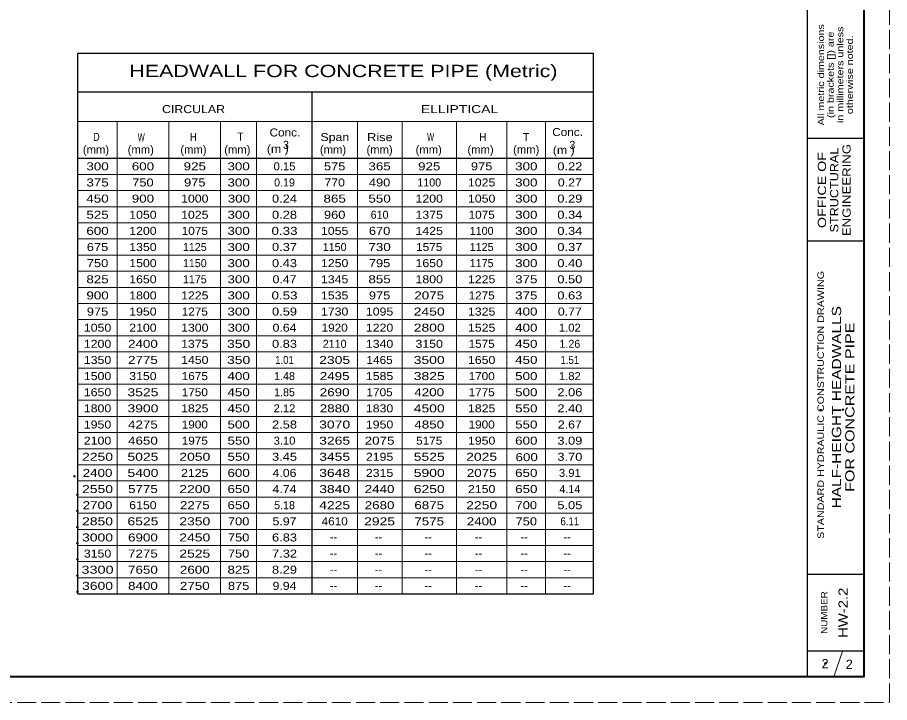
# Model space of a CAD drawing. Extents: x 685.4 to 719.4, y 1059.8 to 1105.8.
# Drawn here: x 702.44 to 719.44, y 1059.77 to 1073.13 of the extents above; entities that cross this region are included whole.
import ezdxf
from ezdxf.enums import TextEntityAlignment as Align

# ---------------------------------------------------------------- set-up
doc = ezdxf.new("R2010")
doc.units = 0
doc.header["$LTSCALE"] = 0.062
doc.header["$PDMODE"] = 32
doc.header["$PDSIZE"] = 0.031
doc.linetypes.add('LONG_DASHED', pattern=[7.5, 6, -1.5])
doc.layers.add('1', color=7, linetype='Continuous', lineweight=13)

msp = doc.modelspace()

# ---------------------------------------------------------------- linework, layer by layer
at = {"layer": '1', "lineweight": 25}
for p, q in [((717.84108, 1060.27067), (717.84108, 1081.27067)), ((718.94108, 1081.27067), (718.94108, 1060.27067)), ((703.62042, 1061.88917), (703.62042, 1072.433)), ((703.62042, 1072.433), (713.67225, 1072.433)), ((713.67225, 1061.88917), (713.67225, 1072.433)), ((703.62042, 1071.68142), (713.67225, 1071.68142)), ((708.18317, 1061.88917), (708.18317, 1071.68142)), ((718.94108, 1070.77067), (717.84108, 1070.77067)), ((703.62042, 1070.38517), (713.67225, 1070.38517)), ((718.94108, 1068.77067), (717.84108, 1068.77067)), ((718.94108, 1062.27067), (717.84108, 1062.27067)), ((703.62042, 1061.88917), (713.67225, 1061.88917)), ((718.94108, 1060.77067), (717.84108, 1060.77067))]:
    msp.add_line(p, q, dxfattribs=at)
at = {"layer": '1'}
for p, q in [((703.62042, 1071.10025), (713.67225, 1071.10025)), ((704.38225, 1061.88917), (704.38225, 1071.10025)), ((705.39258, 1061.88917), (705.39258, 1071.10025)), ((706.40208, 1061.88917), (706.40208, 1071.10025)), ((707.10417, 1061.88917), (707.10417, 1071.10025)), ((709.06775, 1061.88917), (709.06775, 1071.10025)), ((709.93908, 1061.88917), (709.93908, 1071.10025)), ((710.99742, 1061.88917), (710.99742, 1071.10025)), ((711.98225, 1061.88917), (711.98225, 1071.10025)), ((712.735, 1061.88917), (712.735, 1071.10025)), ((703.62042, 1070.0705), (713.67225, 1070.0705)), ((703.62042, 1069.75583), (713.67225, 1069.75583)), ((703.62042, 1069.44117), (713.67225, 1069.44117)), ((703.62042, 1069.1265), (713.67225, 1069.1265)), ((703.62042, 1068.81183), (713.67225, 1068.81183)), ((703.62042, 1068.49717), (713.67225, 1068.49717)), ((703.62042, 1068.1825), (713.67225, 1068.1825)), ((703.62042, 1067.86783), (713.67225, 1067.86783)), ((703.62042, 1067.55317), (713.67225, 1067.55317)), ((703.62042, 1067.2385), (713.67225, 1067.2385)), ((703.62042, 1066.92383), (713.67225, 1066.92383)), ((703.62042, 1066.60917), (713.67225, 1066.60917)), ((703.62042, 1066.2945), (713.67225, 1066.2945)), ((703.62042, 1065.97983), (713.67225, 1065.97983)), ((703.62042, 1065.66517), (713.67225, 1065.66517)), ((703.62042, 1065.3505), (713.67225, 1065.3505)), ((703.62042, 1065.03583), (713.67225, 1065.03583)), ((703.62042, 1064.72117), (713.67225, 1064.72117)), ((703.62042, 1064.4065), (713.67225, 1064.4065)), ((703.62042, 1064.09183), (713.67225, 1064.09183)), ((703.62042, 1063.77717), (713.67225, 1063.77717)), ((703.62042, 1063.4625), (713.67225, 1063.4625)), ((703.62042, 1063.14783), (713.67225, 1063.14783)), ((703.62042, 1062.83317), (713.67225, 1062.83317)), ((703.62042, 1062.5185), (713.67225, 1062.5185)), ((703.62042, 1062.20383), (713.67225, 1062.20383)), ((718.35775, 1060.27067), (718.52442, 1060.77067))]:
    msp.add_line(p, q, dxfattribs=at)
at = {"layer": '1', "linetype": 'LONG_DASHED'}
msp.add_lwpolyline([(685.44108, 1059.77067), (719.44108, 1059.77067), (719.44108, 1081.77067), (685.44108, 1081.77067)], close=True, dxfattribs=at)
at = {"layer": '1', "lineweight": 25}
msp.add_lwpolyline([(718.94108, 1060.27067), (687.44108, 1060.27067), (687.44108, 1081.27067)], dxfattribs=at)
at = {"layer": '1', "lineweight": 40}
msp.add_lwpolyline([(687.44108, 1081.27067), (718.94108, 1081.27067), (718.94108, 1060.27067), (687.44108, 1060.27067)], close=True, dxfattribs=at)
at = {"layer": '1'}
for p in [(718.0985, 1065.47667), (718.53133, 1065.484), (703.55342, 1064.18225), (703.611, 1063.82358), (703.611, 1063.50825), (703.611, 1063.19283), (703.611, 1062.8775), (703.611, 1062.56217), (703.611, 1062.24683), (703.611, 1061.9315), (718.18917, 1060.53442)]:
    msp.add_point(p, dxfattribs=at)

# ---------------------------------------------------------------- texts
for s, height, width, p in [('All metric dimensions', 0.125, 1.25, (718.16492, 1072.01275)), ('in millimeters unless', 0.125, 1.25, (718.53992, 1072.01279)), ('(in brackets []) are', 0.125, 1.25, (718.35242, 1072.01275)), ('otherwise noted.', 0.125, 1.25, (718.72742, 1072.01275)), ('OFFICE OF', 0.16, 1.3, (718.20283, 1069.76512)), ('STRUCTURAL', 0.16, 1.15, (718.44283, 1069.76512)), ('ENGINEERING', 0.16, 1.2, (718.68283, 1069.76521)), ('STANDARD HYDRAULIC CONSTRUCTION DRAWING', 0.125, 1.25, (718.161, 1065.57471)), ('HALF-HEIGHT HEADWALLS', 0.18, 1.25, (718.49692, 1065.53079)), ('FOR CONCRETE PIPE', 0.18, 1.3, (718.75692, 1065.53083)), ('HW-2.2', 0.18, 1.2, (718.62558, 1061.52104)), ('NUMBER', 0.125, 1.15, (718.22808, 1061.52475))]:
    msp.add_text(s, height=height, rotation=90, dxfattribs=dict(at, width=width)).set_placement(p, align=Align.CENTER)
for s, height, width, p in [('HEADWALL FOR CONCRETE PIPE (Metric)', 0.24, 1.3, (704.623, 1071.9675)), ('CIRCULAR', 0.156, 1.15, (705.2605, 1071.26567)), ('ELLIPTICAL', 0.156, 1.3, (710.30542, 1071.26558)), ('D', 0.156, 0.85, (703.91592, 1070.72442)), ('W', 0.156, 0.7, (704.78575, 1070.71775)), ('H', 0.156, 0.9, (705.8025, 1070.72108)), ('Conc.', 0.156, 1.1, (707.35508, 1070.81017)), ('Span', 0.156, 1.15, (708.34775, 1070.72058)), ('Rise', 0.156, 1.2, (709.25583, 1070.71942)), ('W', 0.156, 0.7, (710.4255, 1070.71942)), ('H', 0.156, 0.9, (711.44467, 1070.72108)), ('Conc.', 0.156, 1.1, (712.86567, 1070.818)), ('(mm)', 0.156, 1.05, (703.71675, 1070.47708)), ('(mm)', 0.156, 1.05, (704.58958, 1070.47708)), ('(mm)', 0.156, 1.05, (705.61642, 1070.47708)), ('(mm)', 0.156, 1.05, (706.47208, 1070.47708)), ('(m )', 0.156, 1.15, (707.30267, 1070.49067)), ('(mm)', 0.156, 1.05, (708.33758, 1070.47708)), ('(mm)', 0.156, 1.05, (709.24458, 1070.47708)), ('(mm)', 0.156, 1.05, (710.203, 1070.47708)), ('(mm)', 0.156, 1.05, (711.21275, 1070.47708)), ('(mm)', 0.156, 1.05, (712.10267, 1070.47708)), ('(m )', 0.156, 1.15, (712.87733, 1070.4695))]:
    msp.add_text(s, height=height, dxfattribs=dict(at, width=width)).set_placement(p)
for s, height, p in [('T', 0.156, (706.72317, 1070.73117)), ('T', 0.156, (712.29183, 1070.72108)), ('3', 0.156, (707.61658, 1070.5705)), ('3', 0.156, (713.19967, 1070.56892)), ('--', 0.16, (708.53008, 1062.922)), ('--', 0.16, (709.41008, 1062.922)), ('--', 0.16, (710.37525, 1062.922)), ('--', 0.16, (711.35458, 1062.922)), ('--', 0.16, (712.24875, 1062.922)), ('--', 0.16, (713.08625, 1062.922)), ('--', 0.16, (708.53008, 1062.60467)), ('--', 0.16, (709.41008, 1062.60467)), ('--', 0.16, (710.37525, 1062.60467)), ('--', 0.16, (711.35458, 1062.60467)), ('--', 0.16, (712.24875, 1062.60467)), ('--', 0.16, (713.08625, 1062.60467)), ('--', 0.16, (708.53008, 1062.28733)), ('--', 0.16, (709.41008, 1062.28733)), ('--', 0.16, (710.37525, 1062.28733)), ('--', 0.16, (711.35458, 1062.28733)), ('--', 0.16, (712.24875, 1062.28733)), ('--', 0.16, (713.08625, 1062.28733)), ('--', 0.16, (708.53008, 1061.97)), ('--', 0.16, (709.41008, 1061.97)), ('--', 0.16, (710.37525, 1061.97)), ('--', 0.16, (711.35458, 1061.97)), ('--', 0.16, (712.24875, 1061.97)), ('--', 0.16, (713.08625, 1061.97))]:
    msp.add_text(s, height=height, dxfattribs=at).set_placement(p)
for s, width, p in [('300', 1.25, (704.00254, 1070.14983)), ('600', 1.25, (704.88717, 1070.14983)), ('925', 1.25, (705.89808, 1070.14983)), ('300', 1.25, (706.75288, 1070.14983)), ('0.15', 1.05, (707.64696, 1070.14983)), ('575', 1.2, (708.62483, 1070.14983)), ('365', 1.25, (709.50004, 1070.14983)), ('925', 1.25, (710.46767, 1070.14983)), ('975', 1.2, (711.48992, 1070.14983)), ('300', 1.25, (712.35996, 1070.14983)), ('0.22', 1.2, (713.20887, 1070.14983)), ('375', 1.25, (704.00238, 1069.83517)), ('750', 1.2, (704.88712, 1069.83517)), ('975', 1.2, (705.89808, 1069.83517)), ('300', 1.25, (706.75288, 1069.83517)), ('770', 1.15, (708.62471, 1069.83517)), ('490', 1.2, (709.50004, 1069.83517)), ('1025', 1.15, (711.48987, 1069.83517)), ('300', 1.25, (712.35996, 1069.83517)), ('0.27', 1.15, (713.20892, 1069.83517)), ('450', 1.25, (704.00238, 1069.5205)), ('900', 1.25, (704.88717, 1069.5205)), ('1000', 1.15, (705.898, 1069.5205)), ('300', 1.25, (706.75771, 1069.5205)), ('0.24', 1.2, (707.647, 1069.5205)), ('865', 1.25, (708.62475, 1069.5205)), ('550', 1.25, (709.50017, 1069.5205)), ('1200', 1.15, (710.46767, 1069.5205)), ('1050', 1.15, (711.49004, 1069.5205)), ('300', 1.25, (712.35996, 1069.5205)), ('0.29', 1.2, (713.20896, 1069.5205)), ('525', 1.25, (704.00242, 1069.20583)), ('1050', 1.15, (704.88729, 1069.20583)), ('1025', 1.15, (705.89804, 1069.20583)), ('300', 1.25, (706.75288, 1069.20583)), ('0.28', 1.2, (707.64692, 1069.20583)), ('960', 1.2, (708.62471, 1069.20583)), ('1375', 1.15, (710.46771, 1069.20583)), ('1075', 1.1, (711.49004, 1069.20583)), ('300', 1.25, (712.35996, 1069.20583)), ('0.34', 1.2, (713.20892, 1069.20583)), ('600', 1.25, (704.00233, 1068.89117)), ('1200', 1.15, (704.88717, 1068.89117)), ('1075', 1.1, (705.89821, 1068.89117)), ('300', 1.25, (706.75288, 1068.89117)), ('0.33', 1.25, (707.647, 1068.89117)), ('1055', 1.15, (708.62479, 1068.89117)), ('670', 1.2, (709.50004, 1068.89117)), ('1425', 1.15, (710.46779, 1068.89117)), ('300', 1.25, (712.35996, 1068.89117)), ('0.34', 1.2, (713.20883, 1068.89117)), ('675', 1.2, (704.00238, 1068.5765)), ('1350', 1.15, (704.88712, 1068.5765)), ('300', 1.25, (706.75288, 1068.5765)), ('0.37', 1.2, (707.647, 1068.5765)), ('730', 1.25, (709.50013, 1068.5765)), ('1575', 1.1, (710.46775, 1068.5765)), ('300', 1.25, (712.35996, 1068.5765)), ('0.37', 1.2, (713.20892, 1068.5765)), ('750', 1.2, (704.00238, 1068.26183)), ('1500', 1.15, (704.88729, 1068.26183)), ('300', 1.25, (706.75288, 1068.26183)), ('0.43', 1.2, (707.64692, 1068.26183)), ('1250', 1.15, (708.62479, 1068.26183)), ('795', 1.2, (709.50008, 1068.26183)), ('1650', 1.15, (710.46762, 1068.26183)), ('300', 1.25, (712.35996, 1068.26183)), ('0.40', 1.2, (713.20892, 1068.26183)), ('825', 1.25, (704.00254, 1067.94717)), ('1650', 1.15, (704.88712, 1067.94717)), ('300', 1.25, (706.75288, 1067.94717)), ('0.47', 1.15, (707.647, 1067.94717)), ('1345', 1.15, (708.62471, 1067.94717)), ('855', 1.25, (709.50004, 1067.94717)), ('1800', 1.15, (710.46775, 1067.94717)), ('1225', 1.15, (711.48987, 1067.94717)), ('375', 1.25, (712.35987, 1067.94717)), ('0.50', 1.2, (713.20887, 1067.94717)), ('900', 1.25, (704.00242, 1067.6325)), ('1800', 1.15, (704.88717, 1067.6325)), ('1225', 1.15, (705.89804, 1067.6325)), ('300', 1.25, (706.75288, 1067.6325)), ('0.53', 1.25, (707.64704, 1067.6325)), ('1535', 1.15, (708.62475, 1067.6325)), ('975', 1.2, (709.50008, 1067.6325)), ('2075', 1.25, (710.46779, 1067.6325)), ('1275', 1.1, (711.49004, 1067.6325)), ('375', 1.25, (712.35987, 1067.6325)), ('0.63', 1.2, (713.20883, 1067.6325)), ('975', 1.2, (704.00233, 1067.31783)), ('1950', 1.15, (704.88717, 1067.31783)), ('1275', 1.1, (705.89821, 1067.31783)), ('300', 1.25, (706.75288, 1067.31783)), ('300', 1.25, (706.75288, 1067.31783)), ('0.59', 1.2, (707.64692, 1067.31783)), ('1730', 1.15, (708.62462, 1067.31783)), ('1095', 1.15, (709.50017, 1067.31783)), ('2450', 1.3, (710.46775, 1067.31783)), ('1325', 1.15, (711.48996, 1067.31783)), ('400', 1.25, (712.35983, 1067.31783)), ('0.77', 1.15, (713.20887, 1067.31783)), ('1050', 1.15, (704.00246, 1067.00317)), ('2100', 1.15, (704.88717, 1067.00317)), ('1300', 1.15, (705.89812, 1067.00317)), ('300', 1.25, (706.75288, 1067.00317)), ('0.64', 1.15, (707.647, 1067.00317)), ('1920', 1.1, (708.62479, 1067.00317)), ('1220', 1.15, (709.50008, 1067.00317)), ('2800', 1.3, (710.46775, 1067.00317)), ('1525', 1.15, (711.48996, 1067.00317)), ('400', 1.25, (712.35983, 1067.00317)), ('1.02', 1.05, (713.20879, 1067.00317)), ('1200', 1.15, (704.00233, 1066.6885)), ('2400', 1.25, (704.88717, 1066.6885)), ('1375', 1.15, (705.89804, 1066.6885)), ('350', 1.3, (706.75271, 1066.6885)), ('0.83', 1.2, (707.647, 1066.6885)), ('1340', 1.15, (709.50008, 1066.6885)), ('3150', 1.15, (710.46771, 1066.6885)), ('1575', 1.1, (711.48992, 1066.6885)), ('450', 1.25, (712.35987, 1066.6885)), ('1350', 1.15, (704.00238, 1066.37383)), ('2775', 1.25, (704.88712, 1066.37383)), ('1450', 1.15, (705.89804, 1066.37383)), ('350', 1.3, (706.75271, 1066.37383)), ('1.01', 0.9, (707.64704, 1066.37383)), ('2305', 1.3, (708.62479, 1066.37383)), ('1465', 1.1, (709.50008, 1066.37383)), ('3500', 1.3, (710.46762, 1066.37383)), ('1650', 1.15, (711.48987, 1066.37383)), ('450', 1.25, (712.35987, 1066.37383)), ('1.51', 0.9, (713.20879, 1066.37383)), ('1500', 1.15, (704.00246, 1066.05917)), ('3150', 1.15, (704.88712, 1066.05917)), ('1675', 1.1, (705.89804, 1066.05917)), ('400', 1.25, (706.75275, 1066.05917)), ('2495', 1.25, (708.62471, 1066.05917)), ('1585', 1.15, (709.50004, 1066.05917)), ('3825', 1.3, (710.46775, 1066.05917)), ('1700', 1.1, (711.48996, 1066.05917)), ('500', 1.25, (712.35987, 1066.05917)), ('1.82', 1.05, (713.20887, 1066.05917)), ('1650', 1.15, (704.00229, 1065.7445)), ('3525', 1.3, (704.88712, 1065.7445)), ('1750', 1.1, (705.89804, 1065.7445)), ('450', 1.25, (706.75279, 1065.7445)), ('2690', 1.25, (708.62471, 1065.7445)), ('1705', 1.1, (709.50021, 1065.7445)), ('4200', 1.25, (710.46767, 1065.7445)), ('1775', 1.1, (711.48996, 1065.7445)), ('500', 1.25, (712.35987, 1065.7445)), ('2.06', 1.2, (713.20883, 1065.7445)), ('1800', 1.15, (704.00242, 1065.42983)), ('3900', 1.3, (704.88712, 1065.42983)), ('1825', 1.15, (705.89808, 1065.42983)), ('450', 1.25, (706.75279, 1065.42983)), ('2.12', 1.05, (707.64688, 1065.42983)), ('2880', 1.25, (708.62471, 1065.42983)), ('1830', 1.15, (709.50017, 1065.42983)), ('4500', 1.3, (710.46775, 1065.42983)), ('1825', 1.15, (711.48992, 1065.42983)), ('550', 1.25, (712.35992, 1065.42983)), ('2.40', 1.2, (713.20883, 1065.42983)), ('1950', 1.15, (704.00242, 1065.11517)), ('4275', 1.25, (704.88712, 1065.11517)), ('1900', 1.1, (705.89812, 1065.11517)), ('500', 1.25, (706.75271, 1065.11517)), ('2.58', 1.2, (707.647, 1065.11517)), ('3070', 1.3, (708.62475, 1065.11517)), ('1950', 1.15, (709.50008, 1065.11517)), ('4850', 1.25, (710.46767, 1065.11517)), ('1900', 1.1, (711.48996, 1065.11517)), ('550', 1.25, (712.35992, 1065.11517)), ('2.67', 1.15, (713.20892, 1065.11517)), ('2100', 1.15, (704.00233, 1064.8005)), ('4650', 1.25, (704.88717, 1064.8005)), ('1975', 1.1, (705.89817, 1064.8005)), ('550', 1.25, (706.75283, 1064.8005)), ('3.10', 1.05, (707.64704, 1064.8005)), ('3265', 1.3, (708.62471, 1064.8005)), ('2075', 1.25, (709.50013, 1064.8005)), ('5175', 1.1, (710.46775, 1064.8005)), ('1950', 1.15, (711.48992, 1064.8005)), ('600', 1.25, (712.35983, 1064.8005)), ('3.09', 1.2, (713.20887, 1064.8005)), ('2250', 1.3, (704.00254, 1064.48583)), ('5025', 1.3, (704.88729, 1064.48583)), ('2050', 1.3, (705.89821, 1064.48583)), ('550', 1.25, (706.75283, 1064.48583)), ('3.45', 1.2, (707.64688, 1064.48583)), ('3455', 1.3, (708.62479, 1064.48583)), ('2195', 1.15, (709.50017, 1064.48583)), ('5525', 1.3, (710.46767, 1064.48583)), ('2025', 1.3, (711.48987, 1064.48583)), ('600', 1.25, (712.3675, 1064.47858)), ('3.70', 1.2, (713.20892, 1064.48583)), ('2400', 1.25, (704.00242, 1064.17117)), ('5400', 1.3, (704.88717, 1064.17117)), ('2125', 1.15, (705.89804, 1064.17117)), ('600', 1.25, (706.75275, 1064.17117)), ('4.06', 1.15, (707.647, 1064.17117)), ('3648', 1.3, (708.62471, 1064.17117)), ('2315', 1.15, (709.50013, 1064.17117)), ('5900', 1.3, (710.46775, 1064.17117)), ('2075', 1.25, (711.48996, 1064.17117)), ('650', 1.25, (712.35987, 1064.17117)), ('3.91', 1.05, (713.20896, 1064.17117)), ('2550', 1.3, (704.00238, 1063.8565)), ('5775', 1.25, (704.88717, 1063.8565)), ('2200', 1.3, (705.89808, 1063.8565)), ('650', 1.25, (706.75279, 1063.8565)), ('4.74', 1.15, (707.647, 1063.8565)), ('3840', 1.3, (708.62471, 1063.8565)), ('2440', 1.25, (709.50008, 1063.8565)), ('6250', 1.3, (710.46775, 1063.8565)), ('2150', 1.15, (711.49004, 1063.8565)), ('650', 1.25, (712.35987, 1063.8565)), ('2700', 1.25, (704.00233, 1063.54183)), ('6150', 1.15, (704.88712, 1063.54183)), ('2275', 1.25, (705.89812, 1063.54183)), ('650', 1.25, (706.75279, 1063.54183)), ('4225', 1.3, (708.62475, 1063.54183)), ('2680', 1.25, (709.50013, 1063.54183)), ('6875', 1.25, (710.46775, 1063.54183)), ('2250', 1.3, (711.49004, 1063.54183)), ('700', 1.2, (712.35987, 1063.54183)), ('5.05', 1.2, (713.20887, 1063.54183)), ('2850', 1.3, (704.00233, 1063.22717)), ('6525', 1.3, (704.88712, 1063.22717)), ('2350', 1.3, (705.89796, 1063.22717)), ('700', 1.2, (706.75279, 1063.22717)), ('5.97', 1.15, (707.64692, 1063.22717)), ('4610', 1.1, (708.62467, 1063.22717)), ('2925', 1.3, (709.50008, 1063.22717)), ('7575', 1.25, (710.46775, 1063.22717)), ('2400', 1.25, (711.48992, 1063.22717)), ('750', 1.2, (712.35979, 1063.22717)), ('6.11', 0.9, (713.20892, 1063.22717)), ('3000', 1.3, (704.00242, 1062.9125)), ('6900', 1.25, (704.88721, 1062.9125)), ('2450', 1.3, (705.89808, 1062.9125)), ('750', 1.2, (706.75271, 1062.9125)), ('6.83', 1.2, (707.647, 1062.9125)), ('3150', 1.15, (704.00238, 1062.59783)), ('7275', 1.25, (704.88712, 1062.59783)), ('2525', 1.3, (705.89821, 1062.59783)), ('750', 1.2, (706.75271, 1062.59783)), ('7.32', 1.2, (707.64688, 1062.59783)), ('3300', 1.35, (704.0025, 1062.28317)), ('7650', 1.25, (704.88721, 1062.28317)), ('2600', 1.25, (705.89808, 1062.28317)), ('825', 1.25, (706.75288, 1062.28317)), ('8.29', 1.2, (707.64696, 1062.28317)), ('3600', 1.3, (704.00233, 1061.9685)), ('8400', 1.25, (704.88721, 1061.9685)), ('2750', 1.25, (705.89812, 1061.9685)), ('875', 1.2, (706.75279, 1061.9685)), ('9.94', 1.15, (707.647, 1061.9685))]:
    msp.add_text(s, height=0.156, dxfattribs=dict(at, width=width)).set_placement(p, align=Align.CENTER)
for s, height, p in [('0.19', 0.156, (707.64704, 1069.83517)), ('1100', 0.156, (710.46771, 1069.83517)), ('610', 0.156, (709.50013, 1069.20583)), ('1100', 0.156, (711.48987, 1068.89117)), ('1125', 0.156, (705.89812, 1068.5765)), ('1150', 0.156, (708.62479, 1068.5765)), ('1125', 0.156, (711.48996, 1068.5765)), ('1150', 0.156, (705.89812, 1068.26183)), ('1175', 0.156, (711.49004, 1068.26183)), ('1175', 0.156, (705.89821, 1067.94717)), ('2110', 0.156, (708.62471, 1066.6885)), ('1.26', 0.156, (713.20892, 1066.6885)), ('1.48', 0.156, (707.647, 1066.05917)), ('1.85', 0.156, (707.647, 1065.7445)), ('4.14', 0.156, (713.20883, 1063.8565)), ('5.18', 0.156, (707.647, 1063.54183)), ('2', 0.18, (718.18554, 1060.44075)), ('2', 0.18, (718.65638, 1060.42817))]:
    msp.add_text(s, height=height, dxfattribs=at).set_placement(p, align=Align.CENTER)

doc.saveas('drawing.dxf')
